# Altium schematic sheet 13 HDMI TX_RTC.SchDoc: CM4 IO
size 297 x 209 mm; Page Create Date: March  8, 1995; Page Number: 13; Page Size: A4; Comment: radxa_1010; Page Count: 19; RevCode: V1.10; Doc: 13 HDMI TX/RTC; DsnPath: D:\WMS\黄工\[RC126]CM4_IO_V1.10\[RC126]_V1.10\CM4 IO_V1.10.DSN; SchematicName: CM4 IO V1.10; PageName: 13 HDMI TX/RTC; PageSize: A4; TopSchematic: True
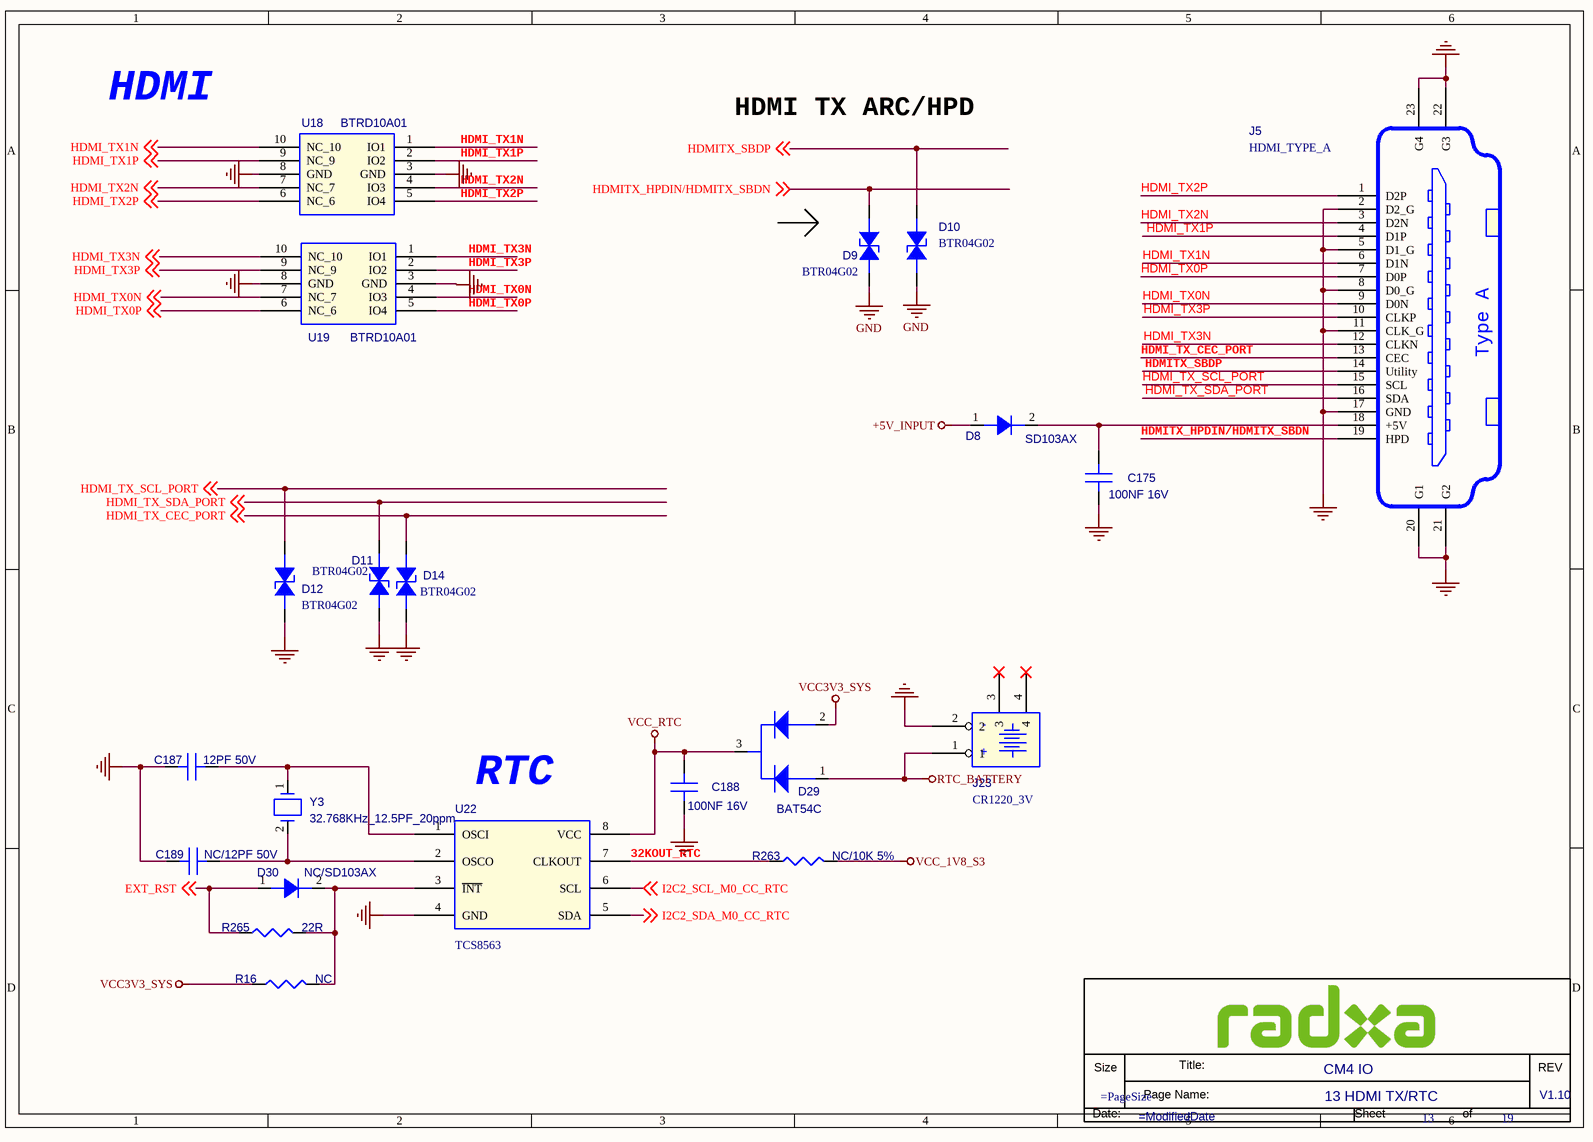
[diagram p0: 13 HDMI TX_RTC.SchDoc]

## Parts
*  Doc: 13 HDMI TX/RTC  RevCode: V1.10  Title: CM4 IO  Page Number: 13  Page Count: 19  (hidden comment: radxa_1010)  (graphical)
C175  100NF 16V  [C0201]
C187  12PF 50V  [C0201]
C188  100NF 16V  [C0201]
C189  NC/12PF 50V  [C0201]
D8  SD103AX  [SOD_523]
D9  BTR04G02  [DFN1006-2L]
D10  BTR04G02  [DFN1006-2L]
D11  BTR04G02  [DFN1006-2L]
D12  BTR04G02  [DFN1006-2L]
D14  BTR04G02  [DFN1006-2L]
D29  BAT54C  [23ACA]
D30  NC/SD103AX  [SOD_523]
J5  HDMI_TYPE_A  [CON_HDMI_TH_19P_STA]
J23  CR1220_3V  [BAT_SM2_12X2]
R16  NC  [R0402]
R263  NC/10K 5%  [R0402]
R265  22R  [R0402]
U18  BTRD10A01  [SON10_0D5_1]
U19  BTRD10A01  [SON10_0D5_1]
U22  TCS8563  [MSOP8_0D65_3]
Y3  32.768KHz_12.5PF_20ppm  [OSC_SM2_3D2X1D5]

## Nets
+5V_INPUT: D8.1(A)
GND: C175.2(B) C187.1(A) C188.2(B) C189.1(A) D9.2(CATHODE) D10.2(CATHODE) D11.2(CATHODE) D12.2(CATHODE) D14.2(CATHODE) J5.2(D2_G) J5.5(D1_G) J5.8(D0_G) J5.11(CLK_G) J5.17(GND) J5.20(G1) J5.21(G2) J5.22(G3) J5.23(G4) J23.2 U18.3(GND) U18.8(GND) U19.3(GND) U19.8(GND) U22.4(GND)
RTC_BATTERY: D29.1(A1) J23.1
VCC3V3_SYS: D29.2(A2) R16.1
VCC_1V8_S3: R263.1
VCC_RTC: C188.1(A) D29.3(C) U22.8(VCC)
32KOUT_RTC: R263.2 U22.7(CLKOUT)
EXT_RST: D30.1(A) R265.1 ; off-sheet EXT_RST
HDMI_TX0N: J5.9(D0N) U19.4(IO3) U19.7(NC_7) ; off-sheet HDMI_TX0N
HDMI_TX0P: J5.7(D0P) U19.5(IO4) U19.6(NC_6) ; off-sheet HDMI_TX0P
HDMI_TX1N: J5.6(D1N) U18.1(IO1) U18.10(NC_10) ; off-sheet HDMI_TX1N
HDMI_TX1P: J5.4(D1P) U18.2(IO2) U18.9(NC_9) ; off-sheet HDMI_TX1P
HDMI_TX2N: J5.3(D2N) U18.4(IO3) U18.7(NC_7) ; off-sheet HDMI_TX2N
HDMI_TX2P: J5.1(D2P) U18.5(IO4) U18.6(NC_6) ; off-sheet HDMI_TX2P
HDMI_TX3N: J5.12(CLKN) U19.1(IO1) U19.10(NC_10) ; off-sheet HDMI_TX3N
HDMI_TX3P: J5.10(CLKP) U19.2(IO2) U19.9(NC_9) ; off-sheet HDMI_TX3P
HDMI_TX_CEC_PORT: D14.1(ANODE) J5.13(CEC) ; off-sheet HDMI_TX_CEC_PORT
HDMI_TX_SCL_PORT: D12.1(ANODE) J5.15(SCL) ; off-sheet HDMI_TX_SCL_PORT
HDMI_TX_SDA_PORT: D11.1(ANODE) J5.16(SDA) ; off-sheet HDMI_TX_SDA_PORT
HDMITX_HPDIN/HDMITX_SBDN: D9.1(ANODE) J5.19(HPD) ; off-sheet HDMITX_HPDIN/HDMITX_SBDN
HDMITX_SBDP: D10.1(ANODE) J5.14(Utility) ; off-sheet HDMITX_SBDP
I2C2_SCL_M0_CC_RTC: U22.6(SCL) ; off-sheet I2C2_SCL_M0_CC_RTC
I2C2_SDA_M0_CC_RTC: U22.5(SDA) ; off-sheet I2C2_SDA_M0_CC_RTC
NetC175_1: C175.1(A) D8.2(K) J5.18(+5V)
NetC187_2: C187.2(B) U22.1(OSCI) Y3.1
NetC189_2: C189.2(B) U22.2(OSCO) Y3.2
NetD30_2: D30.2(K) R16.2 R265.2 U22.3(~{INT})

Not connected (* = marked no-connect by the designer): J23 3* 4*

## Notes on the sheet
- HDMI
- HDMI TX ARC/HPD
- (near U22) RTC

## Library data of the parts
C175 = C: SMD  0201  100NF  16V  X5R  ±20%  ROHS; PARTS: 1; Part Reference: C175; Part Number: A1C01.00099; OriginalSymbolOrigin: (0,30); PKG_TYPE: CAP2-100-250; LEVEL: STD; PINSWAP: (A,B); Preferred: 6715f349cd0bc5
C187 = C: SMD  0201  12PF  50V  COG  ±5%  ROHS; PARTS: 1; Part Reference: C187; Part Number: A1C01.00105; OriginalSymbolOrigin: (0,30); PKG_TYPE: CAP2-100-250; LEVEL: STD; PINSWAP: (A,B)
C188 = C: SMD  0201  100NF  16V  X5R  ±20%  ROHS; PARTS: 1; Part Reference: C188; Part Number: A1C01.00099; OriginalSymbolOrigin: (0,30); PKG_TYPE: CAP2-100-250; LEVEL: STD; PINSWAP: (A,B); Preferred: 6715f349cd0bc5
C189 = C: SMD  0201  12PF  50V  COG  ±5%  ROHS; PARTS: 1; Part Reference: C189; Part Number: A1C01.00105; OriginalSymbolOrigin: (0,30); PKG_TYPE: CAP2-100-250; LEVEL: STD; PINSWAP: (A,B)
D8 = DIODE_Dup1: SMD  编带  SOD-523  SD103AX  CJ  ROHS; Part Reference: D8; Part Number: A1D02.00049; Manufacturer: 长电; RK PN: B5819WS; Priority: A
D9 = ESD: SMD  编带  0402  BTR04G02  B-tron  ROHS; Part Reference: D9; Part Number: A1D02.00002; Parameter: ESD-台舟 ESD5341N-封装 esd0402; ID: DE-E0004; Temp Coeff: -50℃ ~ +125℃; PCB Footprint: ESD_D0402
D10 = ESD: SMD  编带  0402  BTR04G02  B-tron  ROHS; Part Reference: D10; Part Number: A1D02.00002; Parameter: ESD-台舟 ESD5341N-封装 esd0402; ID: DE-E0004; Temp Coeff: -50℃ ~ +125℃; PCB Footprint: ESD_D0402
D11 = ESD: SMD  编带  0402  BTR04G02  B-tron  ROHS; Part Reference: D11; Part Number: A1D02.00002; Parameter: ESD-台舟 ESD5341N-封装 esd0402; ID: DE-E0004; Temp Coeff: -50℃ ~ +125℃; PCB Footprint: ESD_D0402
D12 = ESD: SMD  编带  0402  BTR04G02  B-tron  ROHS; Part Reference: D12; Part Number: A1D02.00002; Parameter: ESD-台舟 ESD5341N-封装 esd0402; ID: DE-E0004; Temp Coeff: -50℃ ~ +125℃; PCB Footprint: ESD_D0402
D14 = ESD: SMD  编带  0402  BTR04G02  B-tron  ROHS; Part Reference: D14; Part Number: A1D02.00002; Parameter: ESD-台舟 ESD5341N-封装 esd0402; ID: DE-E0004; Temp Coeff: -50℃ ~ +125℃; PCB Footprint: ESD_D0402
D29 = DIODE_S_3P: SMD  编带  SOT-23  BAT54C  30V  0.2A  长电  ROHS; Part Reference: D29; Part Number: A1D02.00096; PCB Footprint: SOT_23; Temp Coeff: -55℃ to +150℃; Preferred: 6715f349cd0bc5
D30 = DIODE_Dup1: SMD  编带  SOD-523  SD103AX  CJ  ROHS; Part Reference: D30; Part Number: A1D02.00049; Manufacturer: 长电; RK PN: B5819WS; Priority: A
J5 = HDMI_TYPE_A: DIP  TYPE-A  19PIN  180度  23*7.8*H16mm  镀镍  有定位柱  脚距6.5mm  4插件固定脚  WLDM-094E  ROHS; Part Reference: J5; Part Number: A1J13.00003; Parameter: 连接器-HDMI公母-19P/型号：10029449-001RLF-封装 hdmia19_hdmi_01a
J23 = CR1220: SMD  电池座  2PIN  15.4*14.2*4.1mm  BS-12-B2AA002  美阳  ROHS; Part Reference: J23; Part Number: A1J14.00013; Temp Coeff: -25℃ to +85℃; Preferred: 6715f349cd0bc5
R16 = R: SMD  0201  10K  1/20W  ±5%  ROHS; Part Reference: R16; Part Number: A1R01.00012; PCB Footprint: R0201; Temp Coeff: －55℃ ~ ＋125℃
R263 = R: SMD  0201  10K  1/20W  ±5%  ROHS; Part Reference: R263; Part Number: A1R01.00012; PCB Footprint: R0201; Temp Coeff: －55℃ ~ ＋125℃
R265 = R: SMD  0201  0R  1/20W  ±5%  ROHS; Part Reference: R265; Part Number: A1R01.00027; PCB Footprint: R0201; Temp Coeff: －55℃ ~ ＋125℃
U18 = BTRD10A01: SMD  编带  DFN2510-10L  BTRD10A01  4Line  0.1pF  B-tron  ROHS; Part Reference: U18; Part Number: A1D02.00106; Temp Coeff: -55℃ to +125℃; Preferred: 6715f349cd0bc5
U19 = BTRD10A01: SMD  编带  DFN2510-10L  BTRD10A01  4Line  0.1pF  B-tron  ROHS; Part Reference: U19; Part Number: A1D02.00106; Temp Coeff: -55℃ to +125℃; Preferred: 6715f349cd0bc5
U22 = TCS8563: SMD  时钟  TCS8563-MH  MSOP8  TCS(汤诚)  ROHS; Part Reference: U22; Part Number: A1I01.00268; Preferred: 6715f349cd0bc5; Temp Coeff: -30℃ to +85℃
Y3 = OSC_2P: SMD  编带  无源  3215  32.768KHz  12.5PF  ±20ppm  TAITIEN  XDMCZLNDDD-32.768KHz  ROHS; Part Reference: Y3; Part Number: A1Y01.00037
